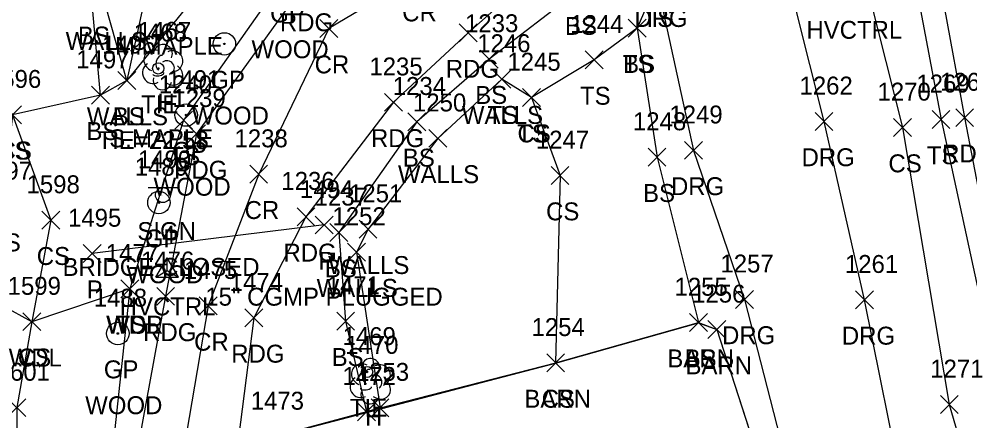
# Model space of a CAD drawing. Extents: x 1512665 to 1513714, y 110636 to 112816.
# Drawn here: x 1513101.2 to 1513207.4, y 110908.3 to 110953.1 of the extents above; entities that cross this region are included whole.
import ezdxf

# ---------------------------------------------------------------- set-up
doc = ezdxf.new("R2010")
doc.units = 0
for name, color, linetype in [('C_A', 7, 'Continuous'), ('C_C', 7, 'Continuous'), ('C_I', 7, 'Continuous'), ('CBP', 7, 'Continuous'), ('CPSM', 7, 'Continuous'), ('D_A', 7, 'Continuous'), ('D_C', 7, 'Continuous'), ('D_I', 7, 'Continuous'), ('D_TIC', 7, 'Continuous'), ('DCP', 7, 'Continuous'), ('L_A', 7, 'Continuous'), ('L_C', 7, 'Continuous'), ('L_I', 7, 'Continuous'), ('L_TIC', 7, 'Continuous'), ('LAWA', 7, 'Continuous'), ('LBC', 7, 'Continuous'), ('LELB', 7, 'Continuous'), ('Level 13', 7, 'Continuous'), ('LTD', 7, 'Continuous'), ('LWS', 7, 'Continuous'), ('P_A', 7, 'Continuous'), ('P_I', 7, 'Continuous'), ('P_TIC', 7, 'Continuous'), ('PET', 7, 'Continuous'), ('PEU', 7, 'Continuous'), ('PRC', 7, 'Continuous'), ('R_A', 7, 'Continuous'), ('R_C', 7, 'Continuous'), ('R_I', 7, 'Continuous'), ('R_TIC', 7, 'Continuous'), ('RDG', 7, 'Continuous'), ('RGP', 7, 'Continuous'), ('S_A', 7, 'Continuous'), ('S_C', 7, 'Continuous'), ('S_I', 7, 'Continuous'), ('SSGN', 7, 'Continuous')]:
    doc.layers.add(name, color=color, linetype=linetype)

msp = doc.modelspace()

# ---------------------------------------------------------------- linework, layer by layer
at = {"layer": 'CBP'}
for centre, radius in [((1513116.75, 110947.59), 0.625), ((1513116.75, 110947.59), 0.0833), ((1513140.08, 110913.72), 0.625), ((1513140.08, 110913.72), 0.0833)]:
    msp.add_circle(centre, radius, dxfattribs=at)
at = {"layer": 'CPSM'}
for p, q in [((1513116.5, 110924.31), (1513117.75, 110926.47)), ((1513116.5, 110924.31), (1513117.75, 110926.47)), ((1513116.5, 110924.31), (1513117.75, 110926.47)), ((1513116.5, 110924.31), (1513117.75, 110926.47)), ((1513116.5, 110924.31), (1513117.75, 110926.47)), ((1513119, 110924.31), (1513117.75, 110926.47)), ((1513117.75, 110925.03), (1513117.75, 110926.47)), ((1513119, 110924.31), (1513117.75, 110926.47)), ((1513117.75, 110925.03), (1513117.75, 110926.47)), ((1513119, 110924.31), (1513117.75, 110926.47)), ((1513117.75, 110925.03), (1513117.75, 110926.47)), ((1513119, 110924.31), (1513117.75, 110926.47)), ((1513117.75, 110925.03), (1513117.75, 110926.47)), ((1513119, 110924.31), (1513117.75, 110926.47)), ((1513117.75, 110925.03), (1513117.75, 110926.47)), ((1513116.5, 110924.31), (1513117.75, 110925.03)), ((1513116.5, 110924.31), (1513117.75, 110925.03)), ((1513116.5, 110924.31), (1513117.75, 110925.03)), ((1513116.5, 110924.31), (1513117.75, 110925.03)), ((1513116.5, 110924.31), (1513117.75, 110925.03)), ((1513117.75, 110925.03), (1513117.75, 110925.03)), ((1513117.75, 110925.03), (1513119, 110924.31)), ((1513117.75, 110925.03), (1513117.75, 110925.03)), ((1513117.75, 110925.03), (1513119, 110924.31)), ((1513117.75, 110925.03), (1513117.75, 110925.03)), ((1513117.75, 110925.03), (1513119, 110924.31)), ((1513117.75, 110925.03), (1513117.75, 110925.03)), ((1513117.75, 110925.03), (1513119, 110924.31)), ((1513117.75, 110925.03), (1513117.75, 110925.03)), ((1513117.75, 110925.03), (1513119, 110924.31)), ((1513116.5, 110924.31), (1513119, 110924.31)), ((1513116.5, 110924.31), (1513119, 110924.31)), ((1513116.5, 110924.31), (1513119, 110924.31)), ((1513116.5, 110924.31), (1513119, 110924.31)), ((1513116.5, 110924.31), (1513119, 110924.31))]:
    msp.add_line(p, q, dxfattribs=at)
at = {"layer": 'D_TIC'}
for points in [[(1513134.28, 110929.12), (1513136.28, 110931.12)], [(1513136.28, 110929.12), (1513134.28, 110931.12)], [(1513108.38, 110925.93), (1513110.38, 110927.93)], [(1513110.38, 110925.93), (1513108.38, 110927.93)]]:
    msp.add_lwpolyline(points, dxfattribs=at)
at = {"layer": 'DCP'}
msp.add_lwpolyline([(1513135.28, 110930.12), (1513109.38, 110926.93)], dxfattribs=at)
at = {"layer": 'L_TIC'}
for points in [[(1513169.22, 110951.09), (1513171.22, 110953.09)], [(1513171.22, 110951.09), (1513169.22, 110953.09)], [(1513169.22, 110951.09), (1513171.22, 110953.09)], [(1513171.22, 110951.09), (1513169.22, 110953.09)], [(1513152.71, 110947.63), (1513154.71, 110949.63)], [(1513154.71, 110947.63), (1513152.71, 110949.63)], [(1513164.44, 110947.54), (1513166.44, 110949.54)], [(1513166.44, 110947.54), (1513164.44, 110949.54)], [(1513112.24, 110945.25), (1513114.24, 110947.25)], [(1513114.24, 110945.25), (1513112.24, 110947.25)], [(1513112.24, 110945.25), (1513114.24, 110947.25)], [(1513114.24, 110945.25), (1513112.24, 110947.25)], [(1513154.12, 110945.4), (1513156.12, 110947.4)], [(1513156.12, 110945.4), (1513154.12, 110947.4)], [(1513154.12, 110945.4), (1513156.12, 110947.4)], [(1513156.12, 110945.4), (1513154.12, 110947.4)], [(1513109.3, 110943.6), (1513111.3, 110945.6)], [(1513111.3, 110943.6), (1513109.3, 110945.6)], [(1513109.3, 110943.6), (1513111.3, 110945.6)], [(1513111.3, 110943.6), (1513109.3, 110945.6)], [(1513157.43, 110943.34), (1513159.43, 110945.34)], [(1513159.43, 110943.34), (1513157.43, 110945.34)], [(1513157.43, 110943.34), (1513159.43, 110945.34)], [(1513159.43, 110943.34), (1513157.43, 110945.34)], [(1513099.49, 110941.42), (1513101.49, 110943.42)], [(1513101.49, 110941.42), (1513099.49, 110943.42)], [(1513099.49, 110941.42), (1513101.49, 110943.42)], [(1513101.49, 110941.42), (1513099.49, 110943.42)], [(1513118.59, 110940.82), (1513120.59, 110942.82)], [(1513120.59, 110940.82), (1513118.59, 110942.82)], [(1513144.63, 110940.63), (1513146.63, 110942.63)], [(1513146.63, 110940.63), (1513144.63, 110942.63)], [(1513203.16, 110940.9), (1513205.16, 110942.9)], [(1513205.16, 110940.9), (1513203.16, 110942.9)], [(1513198.85, 110940), (1513200.85, 110942)], [(1513200.85, 110940), (1513198.85, 110942)], [(1513146.98, 110938.79), (1513148.98, 110940.79)], [(1513148.98, 110938.79), (1513146.98, 110940.79)], [(1513171.45, 110936.69), (1513173.45, 110938.69)], [(1513173.45, 110936.69), (1513171.45, 110938.69)], [(1513160.62, 110934.64), (1513162.62, 110936.64)], [(1513162.62, 110934.64), (1513160.62, 110936.64)], [(1513103.75, 110929.66), (1513105.75, 110931.66)], [(1513105.75, 110929.66), (1513103.75, 110931.66)], [(1513135.92, 110928.29), (1513137.92, 110930.29)], [(1513137.92, 110928.29), (1513135.92, 110930.29)], [(1513139.18, 110928.65), (1513141.18, 110930.65)], [(1513141.18, 110928.65), (1513139.18, 110930.65)], [(1513137.9, 110926.1), (1513139.9, 110928.1)], [(1513139.9, 110926.1), (1513137.9, 110928.1)], [(1513112.58, 110921.99), (1513114.58, 110923.99)], [(1513114.58, 110921.99), (1513112.58, 110923.99)], [(1513112.58, 110921.99), (1513114.58, 110923.99)], [(1513114.58, 110921.99), (1513112.58, 110923.99)], [(1513112.58, 110921.99), (1513114.58, 110923.99)], [(1513114.58, 110921.99), (1513112.58, 110923.99)], [(1513101.64, 110918.33), (1513103.64, 110920.33)], [(1513103.64, 110918.33), (1513101.64, 110920.33)], [(1513101.64, 110918.33), (1513103.64, 110920.33)], [(1513103.64, 110918.33), (1513101.64, 110920.33)], [(1513136.68, 110918.39), (1513138.68, 110920.39)], [(1513138.68, 110918.39), (1513136.68, 110920.39)], [(1513176.09, 110918.23), (1513178.09, 110920.23)], [(1513178.09, 110918.23), (1513176.09, 110920.23)], [(1513176.09, 110918.23), (1513178.09, 110920.23)], [(1513178.09, 110918.23), (1513176.09, 110920.23)], [(1513178.12, 110917.46), (1513180.12, 110919.46)], [(1513180.12, 110917.46), (1513178.12, 110919.46)], [(1513160.13, 110913.73), (1513162.13, 110915.73)], [(1513162.13, 110913.73), (1513160.13, 110915.73)], [(1513160.13, 110913.73), (1513162.13, 110915.73)], [(1513162.13, 110913.73), (1513160.13, 110915.73)], [(1513099.96, 110908.74), (1513101.96, 110910.74)], [(1513101.96, 110908.74), (1513099.96, 110910.74)], [(1513140.52, 110908.73), (1513142.52, 110910.73)], [(1513142.52, 110908.73), (1513140.52, 110910.73)], [(1513140.52, 110908.73), (1513142.52, 110910.73)], [(1513142.52, 110908.73), (1513140.52, 110910.73)], [(1513140.52, 110908.73), (1513142.52, 110910.73)], [(1513142.52, 110908.73), (1513140.52, 110910.73)], [(1513204.09, 110909.09), (1513206.09, 110911.09)], [(1513206.09, 110909.09), (1513204.09, 110911.09)], [(1513139.02, 110908.27), (1513141.02, 110910.27)], [(1513141.02, 110908.27), (1513139.02, 110910.27)], [(1513139.02, 110908.27), (1513141.02, 110910.27)], [(1513141.02, 110908.27), (1513139.02, 110910.27)]]:
    msp.add_lwpolyline(points, dxfattribs=at)
at = {"layer": 'LAWA'}
for points in [[(1513113.58, 110922.99), (1513102.64, 110919.33), (1513097.2, 110922.3), (1513094.75, 110907.49), (1513094.45, 110902.07), (1513096.37, 110887.11), (1513095.69, 110871.35), (1513094.56, 110849.81), (1513096.99, 110839.11), (1513095.31, 110829.26)], [(1513113.58, 110922.99), (1513110.98, 110898.72), (1513111.08, 110874.17), (1513108, 110847.38), (1513106.16, 110836.97), (1513101.97, 110832.47), (1513101.11, 110831.18), (1513095.31, 110829.26)]]:
    msp.add_lwpolyline(points, dxfattribs=at)
at = {"layer": 'LBC'}
for points in [[(1513141.52, 110909.73), (1513161.13, 110914.73), (1513177.09, 110919.23), (1513179.12, 110918.46), (1513186.21, 110896.6), (1513183.81, 110895.79), (1513180.34, 110894.91), (1513175.35, 110893.19), (1513159.49, 110888.71), (1513147.82, 110885.55), (1513142.89, 110884.18), (1513140.56, 110883.67), (1513137.34, 110882.9), (1513136.07, 110882.64), (1513129.77, 110906.51)], [(1513141.52, 110909.73), (1513140.02, 110909.27), (1513129.77, 110906.51)]]:
    msp.add_lwpolyline(points, dxfattribs=at)
at = {"layer": 'LELB'}
for points in [[(1513074.29, 111090.89), (1513073.46, 111069.86), (1513077.06, 111044.99), (1513079.13, 111026.94), (1513081.17, 111003.04), (1513084.44, 110991.21), (1513085.92, 110971.63), (1513087.54, 110964.28), (1513094.93, 110950.26), (1513100.49, 110942.42), (1513104.75, 110930.66), (1513102.64, 110919.33), (1513100.96, 110909.74), (1513100.96, 110887.48)], [(1513156.28, 110981.33), (1513147.68, 110975.84), (1513130.86, 110966.12), (1513127.37, 110963.56), (1513113.24, 110946.25), (1513110.3, 110944.6), (1513100.49, 110942.42), (1513099.4, 110932.18), (1513097.2, 110922.3)], [(1513110.3, 110944.6), (1513109.33, 110955.26), (1513103.86, 110962.94), (1513094.41, 110975.3)], [(1513192.44, 110970.36), (1513199.85, 110941), (1513205.09, 110910.09), (1513211.15, 110889.33), (1513207.14, 110888.27), (1513202.19, 110882.03)], [(1513199.08, 110968.9), (1513204.16, 110941.9), (1513211.03, 110910.3), (1513214.77, 110890.32), (1513221.11, 110860.79), (1513225.66, 110841.85), (1513234.54, 110808.65), (1513239.21, 110788.36), (1513247.66, 110759.74)], [(1513170.26, 110966.54), (1513163.73, 110956.34), (1513153.71, 110948.63), (1513145.63, 110941.63), (1513136.92, 110929.29), (1513137.68, 110919.39), (1513140.02, 110909.27)], [(1513116.01, 110958.89), (1513113.24, 110946.25)], [(1513131.47, 110958.73), (1513119.59, 110941.82), (1513113.58, 110922.99)], [(1513172.43, 110957.22), (1513170.22, 110952.09), (1513165.44, 110948.54), (1513158.43, 110944.34), (1513155.12, 110946.4)], [(1513170.22, 110952.09), (1513172.45, 110937.69), (1513177.09, 110919.23)], [(1513158.43, 110944.34), (1513161.62, 110935.64), (1513161.13, 110914.73)]]:
    msp.add_lwpolyline(points, dxfattribs=at)
at = {"layer": 'Level 13'}
for p, q in [((1513161.13, 110914.72), (1513177.09, 110919.22)), ((1513177.09, 110919.22), (1513179.11, 110918.45)), ((1513179.11, 110918.45), (1513186.2, 110896.6)), ((1513129.78, 110906.51), (1513161.13, 110914.72))]:
    msp.add_line(p, q, dxfattribs=at)
at = {"layer": 'LTD'}
for p, q in [((1513117.23, 110947.79), (1513117.23, 110947.79)), ((1513117.23, 110947.79), (1513117.23, 110947.79)), ((1513140.41, 110912.74), (1513140.41, 110912.74)), ((1513140.41, 110912.74), (1513140.41, 110912.74))]:
    msp.add_line(p, q, dxfattribs=at)
for centre in [(1513117.28, 110949.22), (1513140.46, 110914.17)]:
    msp.add_arc(centre, 1.05, 335.5272, 180.9563, dxfattribs=at)
for centre, major_axis, ratio, start_param, end_param in [((1513116.44, 110948.45), (1.21, -0.51), 0.895232, 1.570796, 4.712389), ((1513117.02, 110948.24), (-0.208, -0.792), 0.645439, 3.141593, 6.283185), ((1513118.27, 110948.37), (-1.14, -0.48), 0.949671, 1.570796, 4.712389), ((1513116.15, 110947.08), (0.58, -1.04), 0.959034, 3.141593, 6.283185), ((1513117.73, 110947.62), (-0.5, 0.667), 0.989748, 3.141593, 6.283185), ((1513118.23, 110946.95), (-1.09, 0.79), 0.841452, 1.570796, 4.712389), ((1513116.77, 110947.04), (-0.625, -0.083), 0.423636, 0, 3.141593), ((1513117.23, 110946.29), (0.26, 1.06), 0.942809, 1.570796, 4.712389), ((1513139.62, 110913.41), (1.21, -0.51), 0.895232, 1.570796, 4.712389), ((1513140.2, 110913.2), (-0.208, -0.792), 0.645439, 3.141593, 6.283185), ((1513141.45, 110913.32), (-1.14, -0.48), 0.949671, 1.570796, 4.712389), ((1513139.33, 110912.03), (0.58, -1.04), 0.959034, 3.141593, 6.283185), ((1513140.91, 110912.57), (-0.5, 0.667), 0.989748, 3.141593, 6.283185), ((1513141.41, 110911.91), (-1.09, 0.79), 0.841452, 1.570796, 4.712389), ((1513139.95, 110911.99), (-0.625, -0.083), 0.423636, 0, 3.141593), ((1513140.41, 110911.24), (0.26, 1.06), 0.942809, 1.570796, 4.712389)]:
    msp.add_ellipse(centre, major_axis=major_axis, ratio=ratio, start_param=start_param, end_param=end_param, dxfattribs=at)
at = {"layer": 'LWS'}
for points in [[(1513113.24, 110946.25), (1513110.87, 110954.65), (1513106.11, 110963.52), (1513095.31, 110975.46), (1513093.16, 110995.74), (1513091.91, 111014.04), (1513090.12, 111028.87), (1513090.53, 111044.09)], [(1513155.12, 110946.4), (1513147.98, 110939.79), (1513140.18, 110929.65), (1513138.9, 110927.1), (1513141.52, 110909.73)]]:
    msp.add_lwpolyline(points, dxfattribs=at)
at = {"layer": 'P_TIC'}
for points in [[(1513134.79, 110951.04), (1513136.79, 110953.04)], [(1513136.79, 110951.04), (1513134.79, 110953.04)], [(1513150.37, 110950.55), (1513152.37, 110952.55)], [(1513152.37, 110950.55), (1513150.37, 110952.55)], [(1513142.02, 110942.81), (1513144.02, 110944.81)], [(1513144.02, 110942.81), (1513142.02, 110944.81)], [(1513205.8, 110941.1), (1513207.8, 110943.1)], [(1513207.8, 110941.1), (1513205.8, 110943.1)], [(1513120.04, 110939.29), (1513122.04, 110941.29)], [(1513122.04, 110939.29), (1513120.04, 110941.29)], [(1513126.97, 110934.79), (1513128.97, 110936.79)], [(1513128.97, 110934.79), (1513126.97, 110936.79)], [(1513132.25, 110930.04), (1513134.25, 110932.04)], [(1513134.25, 110930.04), (1513132.25, 110932.04)], [(1513116.58, 110921.16), (1513118.58, 110923.16)], [(1513118.58, 110921.16), (1513116.58, 110923.16)], [(1513121.32, 110920.1), (1513123.32, 110922.1)], [(1513123.32, 110920.1), (1513121.32, 110922.1)], [(1513126.43, 110918.76), (1513128.43, 110920.76)], [(1513128.43, 110918.76), (1513126.43, 110920.76)]]:
    msp.add_lwpolyline(points, dxfattribs=at)
at = {"layer": 'PET'}
msp.add_lwpolyline([(1513181.78, 111131.32), (1513183.34, 111114.05), (1513184.43, 111101.24), (1513188.03, 111069.41), (1513191.64, 111039.85), (1513195.64, 111010.58), (1513196.78, 111002.78), (1513199.52, 110982.68), (1513202.26, 110966.84), (1513206.8, 110942.1), (1513212.83, 110910.79), (1513216.97, 110890.92), (1513223.71, 110861.11), (1513236.04, 110809.07), (1513241.46, 110788.53), (1513249.29, 110760.24)], dxfattribs=at)
at = {"layer": 'PEU'}
for points in [[(1513166.52, 110981.35), (1513152.91, 110972.97), (1513141.65, 110962.52), (1513132.86, 110956.74), (1513121.04, 110940.29), (1513117.58, 110922.16), (1513113.24, 110898.63), (1513114.6, 110873.19), (1513114.57, 110845.12), (1513110, 110827.88), (1513105.72, 110820.37), (1513100.89, 110809.47), (1513086.52, 110797.2)], [(1513170.26, 110966.54), (1513161.21, 110960.3), (1513151.37, 110951.55), (1513143.02, 110943.81), (1513133.25, 110931.04), (1513127.43, 110919.76), (1513124.63, 110897.94), (1513124.88, 110872.67), (1513125.9, 110844.18), (1513126.27, 110821.8), (1513120.03, 110808.38), (1513110.83, 110798.03), (1513092.49, 110788.31), (1513089.55, 110792.99), (1513086.52, 110797.2)]]:
    msp.add_lwpolyline(points, dxfattribs=at)
at = {"layer": 'PRC'}
msp.add_lwpolyline([(1513199.52, 110982.68), (1513185.86, 110980.15), (1513168.39, 110974.83), (1513156.3, 110966.82), (1513145.57, 110957.84), (1513135.79, 110952.04), (1513127.97, 110935.79), (1513122.32, 110921.1), (1513118.39, 110897.94), (1513119.91, 110872.76), (1513120.73, 110844.83), (1513118.95, 110825.04), (1513112.52, 110813.65), (1513105.71, 110804.09), (1513089.55, 110792.99)], dxfattribs=at)
at = {"layer": 'R_TIC'}
for points in [[(1513190.1, 110940.68), (1513192.1, 110942.68)], [(1513192.1, 110940.68), (1513190.1, 110942.68)], [(1513175.53, 110937.45), (1513177.53, 110939.45)], [(1513177.53, 110937.45), (1513175.53, 110939.45)], [(1513181.22, 110920.82), (1513183.22, 110922.82)], [(1513183.22, 110920.82), (1513181.22, 110922.82)], [(1513194.61, 110920.77), (1513196.61, 110922.77)], [(1513196.61, 110920.77), (1513194.61, 110922.77)]]:
    msp.add_lwpolyline(points, dxfattribs=at)
at = {"layer": 'RDG'}
msp.add_lwpolyline([(1513173.34, 110967.11), (1513172.43, 110957.22), (1513176.53, 110938.45), (1513182.22, 110921.82), (1513188.69, 110896.6), (1513200.03, 110899.83), (1513195.61, 110921.77), (1513191.1, 110941.68), (1513186.33, 110960.8), (1513187.14, 110969.63)], dxfattribs=at)
at = {"layer": 'RGP'}
for p, q in [((1513124.14, 110950.33), (1513124.14, 110950.33)), ((1513119.87, 110942.39), (1513119.87, 110942.39)), ((1513116.83, 110932.62), (1513116.83, 110932.62)), ((1513112.24, 110918.01), (1513112.24, 110918.01))]:
    msp.add_line(p, q, dxfattribs=at)
for centre, radius in [((1513124.14, 110950.33), 1.25), ((1513124.14, 110950.33), 0.0833), ((1513119.87, 110942.39), 1.25), ((1513119.87, 110942.39), 0.0833), ((1513116.83, 110932.62), 1.25), ((1513116.83, 110932.62), 0.0833), ((1513112.24, 110918.01), 1.25), ((1513112.24, 110918.01), 0.0833)]:
    msp.add_circle(centre, radius, dxfattribs=at)
at = {"layer": 'SSGN'}
for p, q in [((1513115.64, 110934.29), (1513118.97, 110934.29)), ((1513117.28, 110933.46), (1513117.28, 110933.46))]:
    msp.add_line(p, q, dxfattribs=at)
msp.add_circle((1513117.28, 110933.46), 0.833, dxfattribs=at)

# ---------------------------------------------------------------- texts
at = {"layer": 'C_A'}
for s, p in [('HVCTRL', (1513189.13, 110950.9)), ('TIE', (1513114.83, 110942.59)), ('HVCTRL', (1513112.45, 110920.03)), ('HVCTRL', (1513112.45, 110920.03)), ('HVCTRL', (1513112.45, 110920.03)), ('HVCTRL', (1513112.45, 110920.03)), ('HVCTRL', (1513112.45, 110920.03)), ('TIE', (1513138.16, 110908.72))]:
    msp.add_text(s, height=2, dxfattribs=at).set_placement(p)
at = {"layer": 'C_C'}
msp.add_text('TIE=22.58', height=2, dxfattribs=at).set_placement((1513109.98, 110938.59))
at = {"layer": 'C_I'}
for s, p in [('1468', (1513114.01, 110950.59)), ('4', (1513117.19, 110928.03)), ('4', (1513117.19, 110928.03)), ('4', (1513117.19, 110928.03)), ('4', (1513117.19, 110928.03)), ('4', (1513117.19, 110928.03)), ('1469', (1513137.34, 110916.72))]:
    msp.add_text(s, height=2, dxfattribs=at).set_placement(p)
at = {"layer": 'D_A'}
for p in [(1513134.65, 110925.12), (1513108.76, 110921.93)]:
    msp.add_text('P', height=2, dxfattribs=at).set_placement(p)
at = {"layer": 'D_C'}
msp.add_text('15" CGMP PLUGGED', height=2, dxfattribs=at).set_placement((1513122.01, 110921.12))
at = {"layer": 'D_I'}
for s, p in [('1494', (1513132.58, 110933.12)), ('1495', (1513106.68, 110929.93))]:
    msp.add_text(s, height=2, dxfattribs=at).set_placement(p)
at = {"layer": 'L_A'}
for s, p in [('TS', (1513170.84, 110952.22)), ('BS', (1513162.17, 110951.34)), ('BS', (1513107.78, 110950.26)), ('WALLS', (1513106.42, 110949.65)), ('TS', (1513168.63, 110947.09)), ('BS', (1513168.66, 110947.09)), ('BS', (1513152.15, 110943.63)), ('H', (1513116.66, 110942.79)), ('TS', (1513163.85, 110943.54)), ('WALLS', (1513108.78, 110941.25)), ('BS', (1513111.68, 110941.25)), ('WALLS', (1513150.66, 110941.4)), ('TS', (1513153.53, 110941.4)), ('BS', (1513108.74, 110939.6)), ('BS', (1513108.74, 110939.6)), ('TS', (1513156.84, 110939.34)), ('CS', (1513156.87, 110939.34)), ('CS', (1513098.93, 110937.42)), ('BS', (1513098.93, 110937.42)), ('TS', (1513118, 110936.82)), ('BS', (1513144.07, 110936.63)), ('TS', (1513202.57, 110936.9)), ('CS', (1513198.29, 110936)), ('WALLS', (1513143.52, 110934.79)), ('BS', (1513170.89, 110932.69)), ('CS', (1513160.06, 110930.64)), ('BS', (1513097.84, 110927.18)), ('CS', (1513103.19, 110925.66)), ('WALLS', (1513135.73, 110924.65)), ('BS', (1513135.36, 110924.29)), ('WALLS', (1513134.44, 110922.1)), ('WDR', (1513110.94, 110917.99)), ('WDL', (1513110.99, 110917.99)), ('TS', (1513111.99, 110917.99)), ('WDL', (1513100.05, 110914.33)), ('CS', (1513101.08, 110914.33)), ('BS', (1513136.12, 110914.39)), ('BARN', (1513173.6, 110914.23)), ('BS', (1513175.53, 110914.23)), ('BARN', (1513175.63, 110913.46)), ('BARN', (1513157.64, 110909.73)), ('CS', (1513159.57, 110909.73)), ('H', (1513139.84, 110907.74))]:
    msp.add_text(s, height=2, dxfattribs=at).set_placement(p)
at = {"layer": 'L_C'}
for s, p in [('M.MAPLE', (1513111.93, 110949.11)), ('S.MAPLE', (1513111.29, 110938.79))]:
    msp.add_text(s, height=2, dxfattribs=at).set_placement(p)
at = {"layer": 'L_I'}
for s, p in [('1233', (1513151.01, 110951.63)), ('1244', (1513162.75, 110951.54)), ('1467', (1513114.49, 110950.79)), ('1496', (1513110.49, 110949.25)), ('1496', (1513110.49, 110949.25)), ('1246', (1513152.37, 110949.4)), ('1246', (1513152.37, 110949.4)), ('1497', (1513107.6, 110947.6)), ('1497', (1513107.6, 110947.6)), ('1245', (1513155.74, 110947.34)), ('1245', (1513155.74, 110947.34)), ('1596', (1513097.74, 110945.42)), ('1596', (1513097.74, 110945.42)), ('1240', (1513116.81, 110944.82)), ('1269', (1513201.41, 110944.9)), ('1234', (1513142.94, 110944.63)), ('1270', (1513197.07, 110944)), ('1250', (1513145.2, 110942.79)), ('1248', (1513169.76, 110940.69)), ('1247', (1513158.92, 110938.64)), ('1597', (1513096.71, 110935.18)), ('1598', (1513102.05, 110933.66)), ('1237', (1513134.22, 110932.29)), ('1251', (1513138.06, 110932.65)), ('1252', (1513136.21, 110930.1)), ('1477', (1513110.88, 110925.99)), ('1477', (1513110.88, 110925.99)), ('1477', (1513110.88, 110925.99)), ('1599', (1513099.94, 110922.33)), ('1599', (1513099.94, 110922.33)), ('1471', (1513135.56, 110922.39)), ('1255', (1513174.4, 110922.23)), ('1255', (1513174.4, 110922.23)), ('1256', (1513176.37, 110921.46)), ('1254', (1513158.44, 110917.73)), ('1254', (1513158.44, 110917.73)), ('1470', (1513137.63, 110915.74)), ('1271', (1513202.96, 110913.09)), ('1601', (1513098.71, 110912.74)), ('1472', (1513137.33, 110912.27)), ('1472', (1513137.33, 110912.27)), ('1253', (1513138.82, 110912.73)), ('1253', (1513138.82, 110912.73)), ('1253', (1513138.82, 110912.73)), ('1473', (1513127.08, 110909.51)), ('1473', (1513127.08, 110909.51))]:
    msp.add_text(s, height=2, dxfattribs=at).set_placement(p)
at = {"layer": 'P_A'}
for s, p in [('CR', (1513144, 110952.84)), ('RDG', (1513130.34, 110951.74)), ('CR', (1513134.22, 110947.04)), ('RDG', (1513148.86, 110946.55)), ('RDG', (1513140.51, 110938.81)), ('RDP', (1513204.29, 110937.1)), ('RDG', (1513118.53, 110935.29)), ('CR', (1513126.4, 110930.79)), ('RDG', (1513130.74, 110926.04)), ('RDG', (1513115.07, 110917.16)), ('CR', (1513120.76, 110916.1)), ('RDG', (1513124.91, 110914.76))]:
    msp.add_text(s, height=2, dxfattribs=at).set_placement(p)
at = {"layer": 'P_I'}
for s, p in [('1235', (1513140.33, 110946.81)), ('1268', (1513204.06, 110945.1)), ('1239', (1513118.34, 110943.29)), ('1238', (1513125.27, 110938.79)), ('1236', (1513130.5, 110934.04)), ('1476', (1513114.83, 110925.16)), ('1475', (1513119.63, 110924.1)), ('1474', (1513124.73, 110922.76))]:
    msp.add_text(s, height=2, dxfattribs=at).set_placement(p)
at = {"layer": 'R_A'}
for s, p in [('GP', (1513129.25, 110952.73)), ('DRG', (1513169.92, 110952.22)), ('GP', (1513122.57, 110945.33)), ('GP', (1513118.31, 110937.39)), ('DRG', (1513188.59, 110936.68)), ('DRG', (1513174.01, 110933.45)), ('GP', (1513115.26, 110927.62)), ('DRG', (1513179.71, 110916.82)), ('DRG', (1513193.09, 110916.77)), ('GP', (1513110.68, 110913.01))]:
    msp.add_text(s, height=2, dxfattribs=at).set_placement(p)
at = {"layer": 'R_C'}
for p in [(1513127.17, 110948.73), (1513120.49, 110941.33), (1513116.23, 110933.39), (1513113.19, 110923.62), (1513108.6, 110909.01)]:
    msp.add_text('WOOD', height=2, dxfattribs=at).set_placement(p)
at = {"layer": 'R_I'}
for s, p in [('1491', (1513117.75, 110945.39)), ('1262', (1513188.36, 110944.68)), ('1249', (1513173.83, 110941.45)), ('1489', (1513114.13, 110935.62)), ('1257', (1513179.53, 110924.82)), ('1261', (1513193.43, 110924.77)), ('1488', (1513109.55, 110921.01))]:
    msp.add_text(s, height=2, dxfattribs=at).set_placement(p)
at = {"layer": 'S_A'}
msp.add_text('SIGN', height=2, dxfattribs=at).set_placement((1513114.42, 110928.44))
at = {"layer": 'S_C'}
msp.add_text('BRIDGE CLOSED', height=2, dxfattribs=at).set_placement((1513106.07, 110924.44))
at = {"layer": 'S_I'}
msp.add_text('1490', height=2, dxfattribs=at).set_placement((1513114.48, 110936.44))

doc.saveas('drawing.dxf')
